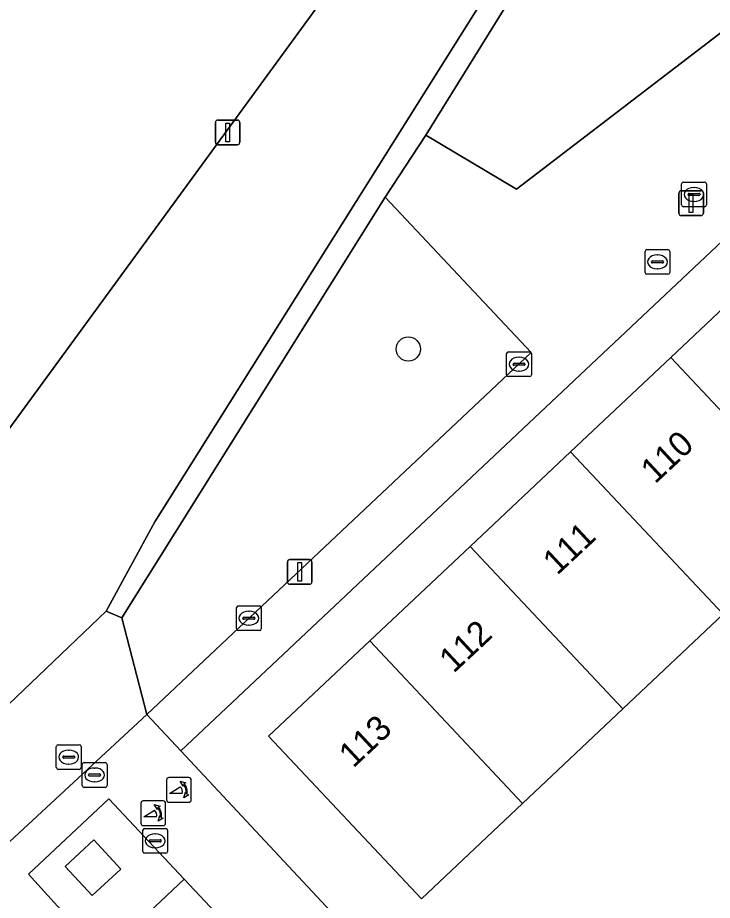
# Model space of a CAD drawing. Extents: x 162542 to 163147, y 380779 to 381521.
# Drawn here: x 162867.22 to 162895.3, y 381283.84 to 381319.49 of the extents above; entities that cross this region are included whole.
import ezdxf

# ---------------------------------------------------------------- set-up
doc = ezdxf.new("R2010")
doc.units = 0
for name, color, linetype in [('IMGEO_Boom', 7, 'Continuous'), ('IMGEO_Brandkraan', 7, 'Continuous'), ('IMGEO_Erf', 7, 'Continuous'), ('IMGEO_Groenvoorziening', 7, 'Continuous'), ('IMGEO_Kolk', 7, 'Continuous'), ('IMGEO_Lichtmast', 7, 'Continuous'), ('IMGEO_Muur', 7, 'Continuous'), ('IMGEO_Pand', 7, 'Continuous'), ('IMGEO_Pand_nummerreeks', 7, 'Continuous'), ('IMGEO_Poller', 7, 'Continuous'), ('IMGEO_Rioolput', 7, 'Continuous'), ('IMGEO_Voetpad_gesloten', 7, 'Continuous'), ('IMGEO_Voetpad_open', 7, 'Continuous')]:
    doc.layers.add(name, color=color, linetype=linetype)

msp = doc.modelspace()

# ---------------------------------------------------------------- linework, layer by layer
at = {"layer": 'IMGEO_Boom'}
msp.add_circle((162883.009, 381306.105), 0.489, dxfattribs=at)
at = {"layer": 'IMGEO_Brandkraan'}
for p, q in [((162892.575, 381309.198), (162892.575, 381310.05)), ((162892.65, 381310.124), (162893.502, 381310.124)), ((162893.063, 381309.904), (162893.088, 381309.904)), ((162893.576, 381310.05), (162893.576, 381309.198)), ((162892.834, 381309.618), (162892.834, 381309.63)), ((162893.272, 381309.581), (162892.874, 381309.581)), ((162892.877, 381309.667), (162893.275, 381309.667)), ((162893.318, 381309.63), (162893.318, 381309.618)), ((162893.502, 381309.124), (162892.65, 381309.124)), ((162893.086, 381309.344), (162893.061, 381309.344))]:
    msp.add_line(p, q, dxfattribs=at)
for points in [[(162892.575, 381309.198), (162892.575, 381310.05)], [(162892.65, 381310.124), (162893.502, 381310.124)], [(162893.576, 381310.05), (162893.576, 381309.198)], [(162893.502, 381309.124), (162892.65, 381309.124)]]:
    msp.add_lwpolyline(points, dxfattribs=at)
for centre, radius, start, end in [((162892.652, 381310.048), 0.0765, 91.552, 178.448), ((162892.652, 381310.048), 0.0765, 91.552, 178.448), ((162893.5, 381310.048), 0.0765, 1.552, 88.448), ((162893.5, 381310.048), 0.0765, 1.552, 88.448), ((162892.874, 381309.627), 0.0403, 85.8775, 175.7526), ((162892.871, 381309.617), 0.0366, 178.938, 274.7102), ((162893.275, 381309.624), 0.043, 264.8664, 352.4533), ((162893.279, 381309.629), 0.0386, 1.7309, 96.639), ((162892.652, 381309.2), 0.0765, 181.552, 268.448), ((162892.652, 381309.2), 0.0765, 181.552, 268.448), ((162893.5, 381309.2), 0.0765, 271.552, 358.448), ((162893.5, 381309.2), 0.0765, 271.552, 358.448)]:
    msp.add_arc(centre, radius, start, end, dxfattribs=at)
for centre, major_axis, ratio, start_param, end_param in [((162893.062, 381309.624), (-0.387, 0.002), 0.722429, 4.712389, 7.853982), ((162893.087, 381309.624), (-0.39, 0.002), 0.717154, 1.570796, 4.712389)]:
    msp.add_ellipse(centre, major_axis=major_axis, ratio=ratio, start_param=start_param, end_param=end_param, dxfattribs=at)
at = {"layer": 'IMGEO_Erf'}
msp.add_lwpolyline([(162942.956, 381330.887), (162939.759, 381327.928), (162937.622, 381330.249), (162940.788, 381333.18), (162938.258, 381335.857), (162930.94, 381343.649), (162873.818, 381289.875), (162880.071, 381283.181), (162886.067, 381276.815), (162886.269, 381276.967), (162890.823, 381281.229), (162891.956, 381280.018), (162891.424, 381279.52), (162892.33, 381278.552), (162888.308, 381274.789), (162889.625, 381273.425), (162889.429, 381273.239), (162902.331, 381259.587), (162950.027, 381304.513), (162959.44, 381313.384), (162948.902, 381324.556), (162946.542, 381327.046), (162943.123, 381330.71)], close=True, dxfattribs=at)
msp.add_lwpolyline([(162924.117, 381322.127), (162920.063, 381318.307), (162916.008, 381314.488), (162911.954, 381310.668), (162907.9, 381306.849), (162903.846, 381303.029), (162899.791, 381299.21), (162895.737, 381295.391), (162891.683, 381291.571), (162887.629, 381287.752), (162883.538, 381283.898), (162877.358, 381290.461), (162881.449, 381294.314), (162885.505, 381298.132), (162889.56, 381301.95), (162893.615, 381305.768), (162897.671, 381309.586), (162901.726, 381313.405), (162905.782, 381317.223), (162909.837, 381321.042)], dxfattribs=at)
at = {"layer": 'IMGEO_Groenvoorziening'}
msp.add_lwpolyline([(162900.206, 381342.771), (162872.763, 381299.129), (162870.795, 381295.515), (162871.434, 381295.246), (162882.08, 381312.238), (162883.712, 381314.744), (162907.437, 381352.98), (162914.15, 381354.131), (162913.608, 381357.077), (162915.016, 381357.986), (162914.563, 381358.416), (162908.261, 381354.192)], dxfattribs=at)
for points in [[(162914.15, 381354.131), (162907.437, 381352.98), (162883.712, 381314.744), (162887.377, 381312.568), (162897.045, 381319.956), (162901.06, 381318.269), (162914.139, 381330.573), (162908.14, 381336.93), (162918.45, 381346.658), (162924.439, 381340.275), (162929.552, 381345.117), (162920.048, 381355.142)], [(162881.067, 381322.31), (162870.141, 381327.128), (162867.886, 381328.147), (162845.981, 381307.523), (162859.527, 381293.151), (162865.246, 381300.672)], [(162872.439, 381291.347), (162887.971, 381305.961), (162882.08, 381312.238), (162871.434, 381295.246)], [(162873.956, 381284.687), (162871.575, 381282.458), (162876.888, 381281.572)]]:
    msp.add_lwpolyline(points, close=True, dxfattribs=at)
at = {"layer": 'IMGEO_Kolk'}
for p, q in [((162894.054, 381311.923), (162894.054, 381312.775)), ((162894.129, 381312.849), (162894.981, 381312.849)), ((162894.542, 381312.629), (162894.567, 381312.629)), ((162895.055, 381312.775), (162895.055, 381311.923)), ((162894.313, 381312.343), (162894.313, 381312.355)), ((162894.751, 381312.306), (162894.353, 381312.306)), ((162894.356, 381312.392), (162894.754, 381312.392)), ((162894.797, 381312.355), (162894.797, 381312.343)), ((162894.565, 381312.069), (162894.54, 381312.069)), ((162894.981, 381311.849), (162894.129, 381311.849)), ((162886.982, 381305.066), (162886.982, 381305.918)), ((162887.057, 381305.992), (162887.909, 381305.992)), ((162887.983, 381305.918), (162887.983, 381305.066)), ((162887.241, 381305.486), (162887.241, 381305.498)), ((162887.284, 381305.535), (162887.682, 381305.535)), ((162887.47, 381305.772), (162887.495, 381305.772)), ((162887.725, 381305.498), (162887.725, 381305.486)), ((162887.679, 381305.449), (162887.281, 381305.449)), ((162887.493, 381305.212), (162887.468, 381305.212)), ((162887.909, 381304.992), (162887.057, 381304.992)), ((162876.067, 381294.806), (162876.067, 381295.658)), ((162876.142, 381295.732), (162876.994, 381295.732)), ((162877.068, 381295.658), (162877.068, 381294.806)), ((162876.326, 381295.226), (162876.326, 381295.238)), ((162876.764, 381295.189), (162876.366, 381295.189)), ((162876.369, 381295.275), (162876.767, 381295.275)), ((162876.555, 381295.512), (162876.58, 381295.512)), ((162876.81, 381295.238), (162876.81, 381295.226)), ((162876.578, 381294.952), (162876.553, 381294.952)), ((162876.994, 381294.732), (162876.142, 381294.732)), ((162872.28, 381285.813), (162872.28, 381286.665)), ((162872.355, 381286.739), (162873.207, 381286.739)), ((162873.281, 381286.665), (162873.281, 381285.813)), ((162872.539, 381286.233), (162872.539, 381286.245)), ((162872.582, 381286.282), (162872.98, 381286.282)), ((162872.768, 381286.519), (162872.793, 381286.519)), ((162873.023, 381286.245), (162873.023, 381286.233)), ((162872.977, 381286.196), (162872.579, 381286.196)), ((162872.791, 381285.959), (162872.766, 381285.959)), ((162873.207, 381285.739), (162872.355, 381285.739))]:
    msp.add_line(p, q, dxfattribs=at)
for points in [[(162894.054, 381311.923), (162894.054, 381312.775)], [(162894.129, 381312.849), (162894.981, 381312.849)], [(162895.055, 381312.775), (162895.055, 381311.923)], [(162894.981, 381311.849), (162894.129, 381311.849)], [(162886.982, 381305.066), (162886.982, 381305.918)], [(162887.057, 381305.992), (162887.909, 381305.992)], [(162887.983, 381305.918), (162887.983, 381305.066)], [(162887.909, 381304.992), (162887.057, 381304.992)], [(162876.067, 381294.806), (162876.067, 381295.658)], [(162876.142, 381295.732), (162876.994, 381295.732)], [(162877.068, 381295.658), (162877.068, 381294.806)], [(162876.994, 381294.732), (162876.142, 381294.732)], [(162872.28, 381285.813), (162872.28, 381286.665)], [(162872.355, 381286.739), (162873.207, 381286.739)], [(162873.281, 381286.665), (162873.281, 381285.813)], [(162873.207, 381285.739), (162872.355, 381285.739)]]:
    msp.add_lwpolyline(points, dxfattribs=at)
for centre, radius, start, end in [((162894.131, 381312.773), 0.0765, 91.552, 178.448), ((162894.131, 381312.773), 0.0765, 91.552, 178.448), ((162894.979, 381312.773), 0.0765, 1.552, 88.448), ((162894.979, 381312.773), 0.0765, 1.552, 88.448), ((162894.353, 381312.352), 0.0403, 85.8775, 175.7526), ((162894.35, 381312.342), 0.0366, 178.938, 274.7102), ((162894.754, 381312.349), 0.043, 264.8664, 352.4533), ((162894.758, 381312.354), 0.0386, 1.7309, 96.639), ((162894.131, 381311.925), 0.0765, 181.552, 268.448), ((162894.131, 381311.925), 0.0765, 181.552, 268.448), ((162894.979, 381311.925), 0.0765, 271.552, 358.448), ((162894.979, 381311.925), 0.0765, 271.552, 358.448), ((162887.059, 381305.916), 0.0765, 91.552, 178.448), ((162887.059, 381305.916), 0.0765, 91.552, 178.448), ((162887.907, 381305.916), 0.0765, 1.552, 88.448), ((162887.907, 381305.916), 0.0765, 1.552, 88.448), ((162887.281, 381305.495), 0.0403, 85.8775, 175.7526), ((162887.686, 381305.497), 0.0386, 1.7309, 96.639), ((162887.278, 381305.485), 0.0366, 178.938, 274.7102), ((162887.682, 381305.492), 0.043, 264.8664, 352.4533), ((162887.059, 381305.068), 0.0765, 181.552, 268.448), ((162887.059, 381305.068), 0.0765, 181.552, 268.448), ((162887.907, 381305.068), 0.0765, 271.552, 358.448), ((162887.907, 381305.068), 0.0765, 271.552, 358.448), ((162876.144, 381295.656), 0.0765, 91.552, 178.448), ((162876.144, 381295.656), 0.0765, 91.552, 178.448), ((162876.992, 381295.656), 0.0765, 1.552, 88.448), ((162876.992, 381295.656), 0.0765, 1.552, 88.448), ((162876.366, 381295.235), 0.0403, 85.8775, 175.7526), ((162876.363, 381295.225), 0.0366, 178.938, 274.7102), ((162876.767, 381295.232), 0.043, 264.8664, 352.4533), ((162876.771, 381295.237), 0.0386, 1.7309, 96.639), ((162876.144, 381294.808), 0.0765, 181.552, 268.448), ((162876.144, 381294.808), 0.0765, 181.552, 268.448), ((162876.992, 381294.808), 0.0765, 271.552, 358.448), ((162876.992, 381294.808), 0.0765, 271.552, 358.448), ((162872.357, 381286.663), 0.0765, 91.552, 178.448), ((162872.357, 381286.663), 0.0765, 91.552, 178.448), ((162873.205, 381286.663), 0.0765, 1.552, 88.448), ((162873.205, 381286.663), 0.0765, 1.552, 88.448), ((162872.579, 381286.242), 0.0403, 85.8775, 175.7526), ((162872.984, 381286.244), 0.0386, 1.7309, 96.639), ((162872.576, 381286.232), 0.0366, 178.938, 274.7102), ((162872.98, 381286.239), 0.043, 264.8664, 352.4533), ((162872.357, 381285.815), 0.0765, 181.552, 268.448), ((162872.357, 381285.815), 0.0765, 181.552, 268.448), ((162873.205, 381285.815), 0.0765, 271.552, 358.448), ((162873.205, 381285.815), 0.0765, 271.552, 358.448)]:
    msp.add_arc(centre, radius, start, end, dxfattribs=at)
for centre, major_axis, ratio, start_param, end_param in [((162894.541, 381312.349), (-0.387, 0.002), 0.722429, 4.712389, 7.853982), ((162894.566, 381312.349), (-0.39, 0.002), 0.717154, 1.570796, 4.712389), ((162887.469, 381305.492), (-0.387, 0.002), 0.722429, 4.712389, 7.853982), ((162887.494, 381305.492), (-0.39, 0.002), 0.717154, 1.570796, 4.712389), ((162876.554, 381295.232), (-0.387, 0.002), 0.722429, 4.712389, 7.853982), ((162876.579, 381295.232), (-0.39, 0.002), 0.717154, 1.570796, 4.712389), ((162872.767, 381286.239), (-0.387, 0.002), 0.722429, 4.712389, 7.853982), ((162872.792, 381286.239), (-0.39, 0.002), 0.717154, 1.570796, 4.712389)]:
    msp.add_ellipse(centre, major_axis=major_axis, ratio=ratio, start_param=start_param, end_param=end_param, dxfattribs=at)
at = {"layer": 'IMGEO_Lichtmast'}
for p, q in [((162875.212, 381314.454), (162875.212, 381315.254)), ((162875.212, 381315.254), (162875.212, 381314.454)), ((162875.312, 381315.354), (162876.102, 381315.354)), ((162876.102, 381315.354), (162875.312, 381315.354)), ((162876.202, 381315.254), (162876.202, 381314.454)), ((162876.202, 381314.454), (162876.202, 381315.254)), ((162876.102, 381314.354), (162875.312, 381314.354)), ((162875.312, 381314.354), (162876.102, 381314.354)), ((162893.942, 381311.596), (162893.942, 381312.396)), ((162893.942, 381312.396), (162893.942, 381311.596)), ((162894.042, 381312.496), (162894.832, 381312.496)), ((162894.832, 381312.496), (162894.042, 381312.496)), ((162894.932, 381312.396), (162894.932, 381311.596)), ((162894.932, 381311.596), (162894.932, 381312.396)), ((162894.832, 381311.496), (162894.042, 381311.496)), ((162894.042, 381311.496), (162894.832, 381311.496)), ((162878.123, 381296.701), (162878.123, 381297.501)), ((162878.123, 381297.501), (162878.123, 381296.701)), ((162878.223, 381297.601), (162879.013, 381297.601)), ((162879.013, 381297.601), (162878.223, 381297.601)), ((162879.113, 381297.501), (162879.113, 381296.701)), ((162879.113, 381296.701), (162879.113, 381297.501)), ((162879.013, 381296.601), (162878.223, 381296.601)), ((162878.223, 381296.601), (162879.013, 381296.601))]:
    msp.add_line(p, q, dxfattribs=at)
for points in [[(162875.632, 381315.229), (162875.782, 381315.229), (162875.782, 381314.479), (162875.632, 381314.479), (162875.632, 381315.229)], [(162894.362, 381312.371), (162894.512, 381312.371), (162894.512, 381311.621), (162894.362, 381311.621), (162894.362, 381312.371)], [(162878.543, 381297.476), (162878.693, 381297.476), (162878.693, 381296.726), (162878.543, 381296.726), (162878.543, 381297.476)]]:
    msp.add_lwpolyline(points, dxfattribs=at)
for centre, start, end in [((162875.312, 381315.254), 90, 180), ((162875.312, 381315.254), 90, 180), ((162876.102, 381315.254), 0, 90), ((162876.102, 381315.254), 360, 90), ((162875.312, 381314.454), 180, 270), ((162875.312, 381314.454), 180, 270), ((162876.102, 381314.454), 270, 0), ((162876.102, 381314.454), 270, 0), ((162894.042, 381312.396), 90, 180), ((162894.042, 381312.396), 90, 180), ((162894.832, 381312.396), 0, 90), ((162894.832, 381312.396), 360, 90), ((162894.042, 381311.596), 180, 270), ((162894.042, 381311.596), 180, 270), ((162894.832, 381311.596), 270, 0), ((162894.832, 381311.596), 270, 0), ((162878.223, 381297.501), 90, 180), ((162878.223, 381297.501), 90, 180), ((162879.013, 381297.501), 0, 90), ((162879.013, 381297.501), 360, 90), ((162878.223, 381296.701), 180, 270), ((162878.223, 381296.701), 180, 270), ((162879.013, 381296.701), 270, 0), ((162879.013, 381296.701), 270, 0)]:
    msp.add_arc(centre, 0.1, start, end, dxfattribs=at)
at = {"layer": 'IMGEO_Muur'}
for points in [[(162883.712, 381314.744), (162907.437, 381352.98), (162914.15, 381354.131)], [(162882.08, 381312.238), (162871.434, 381295.246)], [(162871.434, 381295.246), (162872.439, 381291.347)]]:
    msp.add_lwpolyline(points, dxfattribs=at)
at = {"layer": 'IMGEO_Pand'}
for points in [[(162893.615, 381305.768), (162899.791, 381299.21), (162903.846, 381303.029), (162897.671, 381309.586)], [(162893.615, 381305.768), (162889.56, 381301.95), (162895.737, 381295.391), (162899.791, 381299.21)], [(162885.505, 381298.132), (162891.683, 381291.571), (162895.737, 381295.391), (162889.56, 381301.95)], [(162887.629, 381287.752), (162891.683, 381291.571), (162885.505, 381298.132), (162881.449, 381294.314)], [(162887.629, 381287.752), (162881.449, 381294.314), (162877.358, 381290.461), (162883.538, 381283.898)]]:
    msp.add_lwpolyline(points, close=True, dxfattribs=at)
at = {"layer": 'IMGEO_Poller'}
for p, q in [((162874.144, 381288.792), (162873.336, 381288.792)), ((162874.144, 381288.792), (162873.336, 381288.792)), ((162873.242, 381288.697), (162873.242, 381287.89)), ((162873.242, 381288.697), (162873.242, 381287.89)), ((162874.238, 381287.89), (162874.238, 381288.697)), ((162874.238, 381287.89), (162874.238, 381288.697)), ((162872.204, 381287.756), (162872.204, 381286.949)), ((162872.204, 381287.756), (162872.204, 381286.949)), ((162873.106, 381287.851), (162872.298, 381287.851)), ((162873.106, 381287.851), (162872.298, 381287.851)), ((162873.2, 381286.949), (162873.2, 381287.756)), ((162873.2, 381286.949), (162873.2, 381287.756)), ((162873.336, 381287.795), (162874.144, 381287.795)), ((162873.336, 381287.795), (162874.144, 381287.795)), ((162872.298, 381286.854), (162873.106, 381286.854)), ((162872.298, 381286.854), (162873.106, 381286.854))]:
    msp.add_line(p, q, dxfattribs=at)
for points in [[(162873.877, 381288.148), (162873.364, 381288.148), (162873.794, 381288.423)], [(162873.921, 381288.521), (162873.909, 381288.448), (162873.784, 381288.653)], [(162873.784, 381288.653), (162874.015, 381288.587), (162873.944, 381288.555)], [(162873.937, 381287.976), (162874.003, 381288.207), (162874.033, 381288.139)], [(162874.069, 381288.112), (162874.141, 381288.101), (162873.937, 381287.976)], [(162872.883, 381287.58), (162872.871, 381287.507), (162872.746, 381287.712)], [(162872.746, 381287.712), (162872.977, 381287.646), (162872.906, 381287.614)], [(162872.839, 381287.207), (162872.326, 381287.207), (162872.756, 381287.482)], [(162872.899, 381287.035), (162872.965, 381287.266), (162872.995, 381287.198)], [(162873.031, 381287.171), (162873.103, 381287.16), (162872.899, 381287.035)]]:
    msp.add_lwpolyline(points, dxfattribs=at)
for centre, radius, start, end in [((162873.336, 381288.697), 0.0946, 90, 180), ((162873.336, 381288.697), 0.0946, 90, 180), ((162874.144, 381288.697), 0.0946, 0, 90), ((162874.144, 381288.697), 0.0946, 0, 90), ((162873.549, 381288.198), 0.332, 351.3247, 42.4854), ((162873.563, 381288.208), 0.476, 351.7527, 41.1691), ((162873.563, 381288.208), 0.516, 349.3569, 42.2912), ((162872.298, 381287.756), 0.0946, 90, 180), ((162872.298, 381287.756), 0.0946, 90, 180), ((162873.106, 381287.756), 0.0946, 0, 90), ((162873.106, 381287.756), 0.0946, 0, 90), ((162873.336, 381287.89), 0.0946, 180, 270), ((162873.336, 381287.89), 0.0946, 180, 270), ((162874.144, 381287.89), 0.0946, 270, 0), ((162874.144, 381287.89), 0.0946, 270, 0), ((162872.511, 381287.257), 0.332, 351.3247, 42.4854), ((162872.525, 381287.267), 0.476, 351.7527, 41.1691), ((162872.525, 381287.267), 0.516, 349.3569, 42.2912), ((162872.298, 381286.949), 0.0946, 180, 270), ((162872.298, 381286.949), 0.0946, 180, 270), ((162873.106, 381286.949), 0.0946, 270, 0), ((162873.106, 381286.949), 0.0946, 270, 0)]:
    msp.add_arc(centre, radius, start, end, dxfattribs=at)
at = {"layer": 'IMGEO_Rioolput'}
for p, q in [((162868.786, 381289.196), (162868.786, 381290.048)), ((162868.861, 381290.122), (162869.713, 381290.122)), ((162869.274, 381289.902), (162869.299, 381289.902)), ((162869.787, 381290.048), (162869.787, 381289.196)), ((162869.045, 381289.616), (162869.045, 381289.628)), ((162869.483, 381289.579), (162869.085, 381289.579)), ((162869.088, 381289.665), (162869.486, 381289.665)), ((162869.529, 381289.628), (162869.529, 381289.616)), ((162869.713, 381289.122), (162868.861, 381289.122)), ((162869.297, 381289.342), (162869.272, 381289.342)), ((162869.833, 381288.474), (162869.833, 381289.326)), ((162869.908, 381289.4), (162870.76, 381289.4)), ((162870.321, 381289.18), (162870.346, 381289.18)), ((162870.834, 381289.326), (162870.834, 381288.474)), ((162870.092, 381288.894), (162870.092, 381288.906)), ((162870.53, 381288.857), (162870.132, 381288.857)), ((162870.135, 381288.943), (162870.533, 381288.943)), ((162870.576, 381288.906), (162870.576, 381288.894)), ((162870.76, 381288.4), (162869.908, 381288.4)), ((162870.344, 381288.62), (162870.319, 381288.62))]:
    msp.add_line(p, q, dxfattribs=at)
for points in [[(162868.786, 381289.196), (162868.786, 381290.048)], [(162868.861, 381290.122), (162869.713, 381290.122)], [(162869.787, 381290.048), (162869.787, 381289.196)], [(162869.713, 381289.122), (162868.861, 381289.122)], [(162869.833, 381288.474), (162869.833, 381289.326)], [(162869.908, 381289.4), (162870.76, 381289.4)], [(162870.834, 381289.326), (162870.834, 381288.474)], [(162870.76, 381288.4), (162869.908, 381288.4)]]:
    msp.add_lwpolyline(points, dxfattribs=at)
for centre, radius, start, end in [((162868.863, 381290.046), 0.0765, 91.552, 178.448), ((162868.863, 381290.046), 0.0765, 91.552, 178.448), ((162869.711, 381290.046), 0.0765, 1.552, 88.448), ((162869.711, 381290.046), 0.0765, 1.552, 88.448), ((162869.085, 381289.625), 0.0403, 85.8775, 175.7526), ((162869.082, 381289.615), 0.0366, 178.938, 274.7102), ((162869.486, 381289.622), 0.043, 264.8664, 352.4533), ((162869.49, 381289.627), 0.0386, 1.7309, 96.639), ((162868.863, 381289.198), 0.0765, 181.552, 268.448), ((162868.863, 381289.198), 0.0765, 181.552, 268.448), ((162869.711, 381289.198), 0.0765, 271.552, 358.448), ((162869.711, 381289.198), 0.0765, 271.552, 358.448), ((162869.91, 381289.324), 0.0765, 91.552, 178.448), ((162869.91, 381289.324), 0.0765, 91.552, 178.448), ((162870.758, 381289.324), 0.0765, 1.552, 88.448), ((162870.758, 381289.324), 0.0765, 1.552, 88.448), ((162870.132, 381288.903), 0.0403, 85.8775, 175.7526), ((162870.129, 381288.893), 0.0366, 178.938, 274.7102), ((162870.533, 381288.9), 0.043, 264.8664, 352.4533), ((162870.537, 381288.905), 0.0386, 1.7309, 96.639), ((162869.91, 381288.476), 0.0765, 181.552, 268.448), ((162869.91, 381288.476), 0.0765, 181.552, 268.448), ((162870.758, 381288.476), 0.0765, 271.552, 358.448), ((162870.758, 381288.476), 0.0765, 271.552, 358.448)]:
    msp.add_arc(centre, radius, start, end, dxfattribs=at)
for centre, major_axis, ratio, start_param, end_param in [((162869.273, 381289.622), (-0.387, 0.002), 0.722429, 4.712389, 7.853982), ((162869.298, 381289.622), (-0.39, 0.002), 0.717154, 1.570796, 4.712389), ((162870.32, 381288.9), (-0.387, 0.002), 0.722429, 4.712389, 7.853982), ((162870.345, 381288.9), (-0.39, 0.002), 0.717154, 1.570796, 4.712389)]:
    msp.add_ellipse(centre, major_axis=major_axis, ratio=ratio, start_param=start_param, end_param=end_param, dxfattribs=at)
at = {"layer": 'IMGEO_Voetpad_gesloten'}
msp.add_lwpolyline([(162870.301, 381286.275), (162869.148, 381285.204), (162870.238, 381284.029), (162871.392, 381285.1)], close=True, dxfattribs=at)
at = {"layer": 'IMGEO_Voetpad_open'}
for points in [[(162891.046, 381353.514), (162847.862, 381312.771), (162846.452, 381314.267), (162843.879, 381316.998), (162842.68, 381315.869), (162838.945, 381312.353), (162837.889, 381311.359), (162841.428, 381307.595), (162841.873, 381307.121), (162845.3, 381303.475), (162849.172, 381299.357), (162852.526, 381295.789), (162856.594, 381291.461), (162860.565, 381287.236), (162856.908, 381283.784), (162848.214, 381275.579), (162840.206, 381268.046), (162840.913, 381267.294), (162862.582, 381287.674), (162870.795, 381295.515), (162872.763, 381299.129), (162900.206, 381342.771)], [(162947.383, 381211.626), (162906.029, 381255.574), (162902.331, 381259.587), (162889.429, 381273.239), (162889.625, 381273.425), (162888.308, 381274.789), (162886.269, 381276.967), (162886.067, 381276.815), (162880.071, 381283.181), (162873.818, 381289.875), (162872.439, 381291.347), (162864.115, 381283.64)], [(162907.224, 381242.793), (162899.498, 381250.953), (162897.636, 381252.919), (162892.698, 381258.134), (162890.948, 381260.004), (162888.646, 381262.463), (162874.708, 381277.269), (162872.006, 381280.156), (162870.656, 381281.598), (162867.659, 381284.894), (162870.901, 381287.931), (162873.956, 381284.687), (162876.888, 381281.572), (162878.021, 381280.369), (162891.96, 381265.565), (162892.787, 381264.687), (162896.025, 381261.248), (162900.978, 381255.987), (162902.789, 381254.064), (162910.507, 381245.873)]]:
    msp.add_lwpolyline(points, dxfattribs=at)
for points in [[(162930.94, 381343.649), (162929.552, 381345.117), (162924.439, 381340.275), (162914.139, 381330.573), (162901.06, 381318.269), (162897.045, 381319.956), (162887.377, 381312.568), (162883.712, 381314.744), (162882.08, 381312.238), (162887.971, 381305.961), (162872.439, 381291.347), (162873.818, 381289.875)], [(162845.981, 381307.523), (162867.886, 381328.147), (162883.077, 381342.45), (162893.592, 381339.437), (162891.337, 381336.354), (162881.067, 381322.31), (162865.246, 381300.672), (162866.239, 381294.068), (162862.21, 381290.304), (162859.527, 381293.151)], [(162864.115, 381283.64), (162872.439, 381291.347), (162871.434, 381295.246), (162870.795, 381295.515), (162862.582, 381287.674), (162840.913, 381267.294), (162839.922, 381266.362), (162801.587, 381230.307), (162797.686, 381227.138), (162787.433, 381220.358), (162785.212, 381218.724), (162773.466, 381210.777), (162763.302, 381208.084), (162764.861, 381202.201), (162744.562, 381196.817), (162739.9, 381195.582), (162741.119, 381190.891), (162766.134, 381197.592), (162774.367, 381199.798), (162775.779, 381206.104), (162787.491, 381214.105), (162788.325, 381214.675), (162796.372, 381220.172), (162796.565, 381219.956)], [(162870.901, 381287.931), (162867.659, 381284.894), (162870.656, 381281.598), (162871.575, 381282.458), (162873.956, 381284.687)], [(162871.392, 381285.1), (162870.238, 381284.029), (162869.148, 381285.204), (162870.301, 381286.275)]]:
    msp.add_lwpolyline(points, close=True, dxfattribs=at)

# ---------------------------------------------------------------- texts
at = {"layer": 'IMGEO_Pand_nummerreeks'}
for s, rotation, p in [('110', 43.0251, (162892.983, 381300.634)), ('111', 43.0251, (162889.025, 381296.94)), ('112', 43.0475, (162884.838, 381292.983)), ('113', 43.0251, (162880.783, 381289.152))]:
    msp.add_text(s, height=1, rotation=rotation, dxfattribs=at).set_placement(p)

doc.saveas('drawing.dxf')
